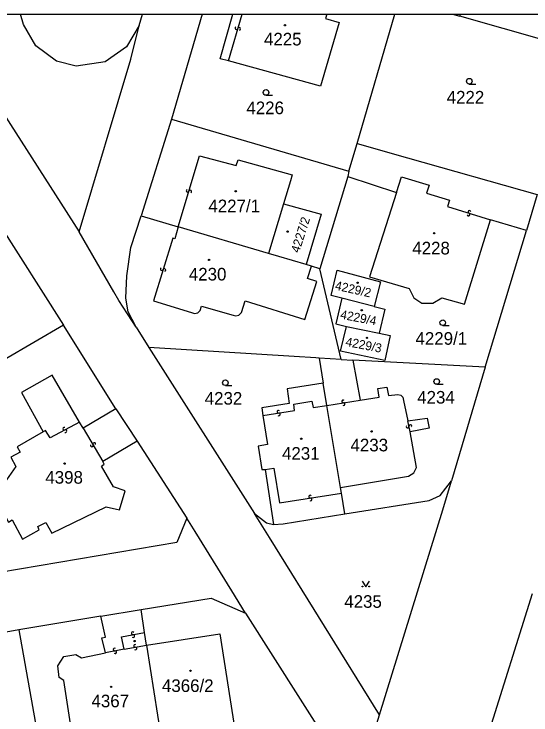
# Model space of a CAD drawing. Extents: x -600391 to -599491, y -1160176 to -1159402.
# Drawn here: x -600015.6 to -599946, y -1159496.1 to -1159401.8 of the extents above; entities that cross this region are included whole.
import ezdxf

# ---------------------------------------------------------------- set-up
doc = ezdxf.new("R2010")
doc.units = 0
for name, color, linetype in [('Level 1', 7, 'Continuous'), ('Level 13', 7, 'Continuous'), ('Level 3', 7, 'Continuous'), ('Level 4', 7, 'Continuous'), ('Level 5', 7, 'Continuous'), ('Vrstva 63', 7, 'Continuous')]:
    doc.layers.add(name, color=color, linetype=linetype)

msp = doc.modelspace()

# ---------------------------------------------------------------- linework, layer by layer
at = {"layer": 'Level 1'}
for p, q in [((-600025.615, -1159401.769), (-600006.83, -1159431.1)), ((-599998.75, -1159403.33), (-599998.285, -1159401.769)), ((-599990.249, -1159401.769), (-599994.38, -1159415.94)), ((-599969.4, -1159419.22), (-599964.303, -1159401.769)), ((-599956.549, -1159401.769), (-599955.56, -1159402.05))]:
    msp.add_line(p, q, dxfattribs=at)
for points in [[(-599998.75, -1159403.33), (-600000.47, -1159406.19), (-600003.32, -1159408.19), (-600007.23, -1159408.8), (-600009.86, -1159408.12), (-600012.67, -1159406.06), (-600014.33, -1159403.17), (-600014.711, -1159401.769)], [(-599986.74, -1159408.06), (-599987.82, -1159407.78), (-599986.115, -1159401.769)], [(-599973.501, -1159401.769), (-599973.67, -1159402.38), (-599971.8, -1159402.92), (-599974.35, -1159411.47), (-599986.74, -1159408.06)], [(-599943.91, -1159405.37), (-599955.56, -1159402.05)], [(-600006.83, -1159431.1), (-599999.85, -1159407.83), (-599998.75, -1159403.33)], [(-599994.38, -1159415.94), (-599998.47, -1159428.92)], [(-599994.38, -1159415.94), (-599970.52, -1159422.92)], [(-599970.52, -1159422.92), (-599969.4, -1159419.22)], [(-599969.4, -1159419.22), (-599962.6, -1159421.11), (-599945.15, -1159426.05)], [(-599970.52, -1159422.92), (-599970.67, -1159423.65)], [(-599970.67, -1159423.65), (-599974.42, -1159436.05)], [(-599970.67, -1159423.65), (-599964.11, -1159425.81)], [(-599964.11, -1159425.81), (-599967.72, -1159437.15), (-599962.41, -1159438.72), (-599961.78, -1159439.97), (-599960.68, -1159440.68), (-599959.19, -1159440.71), (-599958, -1159439.98), (-599954.96, -1159440.83), (-599951.46, -1159429.47)], [(-599945.15, -1159426.05), (-599946.61, -1159430.9)], [(-599979.31, -1159427.32), (-599981.35, -1159434)], [(-599979.31, -1159427.32), (-599974.26, -1159428.69), (-599976.27, -1159435.47)], [(-599999.17, -1159443.94), (-600000.24, -1159441.85), (-600000.55, -1159440.01), (-600000.42, -1159436.99), (-599999.85, -1159433.21), (-599998.47, -1159428.92)], [(-599998.47, -1159428.92), (-599993.49, -1159430.4)], [(-600017.83, -1159429.73), (-600008.95, -1159443.66)], [(-599946.61, -1159430.9), (-599951.46, -1159429.47)], [(-599999.17, -1159443.94), (-600001.48, -1159440.33), (-600002.16, -1159439.16), (-600006.83, -1159431.1)], [(-599981.35, -1159434), (-599993.49, -1159430.4)], [(-599952.16, -1159449.29), (-599946.61, -1159430.9)], [(-599976.27, -1159435.47), (-599979.93, -1159434.39), (-599981.35, -1159434)], [(-599975.55, -1159435.7), (-599976.27, -1159435.47)], [(-599974.42, -1159436.05), (-599975.55, -1159435.7)], [(-599971.57, -1159448.28), (-599974.42, -1159436.05)], [(-599971.45, -1159440), (-599972.91, -1159439.66), (-599972.1, -1159436.26), (-599966.26, -1159437.8), (-599967.11, -1159441.12)], [(-599971.45, -1159440), (-599972.28, -1159443.48), (-599970.83, -1159443.84)], [(-599967.11, -1159441.12), (-599971.45, -1159440)], [(-599967.11, -1159441.12), (-599965.67, -1159441.52), (-599966.43, -1159444.74)], [(-600008.95, -1159443.66), (-600024.96, -1159452.99)], [(-600001.88, -1159454.91), (-600008.95, -1159443.66)], [(-599999.17, -1159443.94), (-599997.46, -1159446.65)], [(-599966.43, -1159444.74), (-599964.95, -1159445.06), (-599965.67, -1159448.43), (-599971.62, -1159447.16), (-599970.83, -1159443.84)], [(-599970.83, -1159443.84), (-599966.43, -1159444.74)], [(-599997.46, -1159446.65), (-599983.21, -1159469.02)], [(-599974.53, -1159448.1), (-599974.95, -1159448.07), (-599977.9, -1159447.88), (-599997.46, -1159446.65)], [(-599974.53, -1159448.1), (-599973.98, -1159451.47)], [(-599971.57, -1159448.28), (-599974.53, -1159448.1)], [(-599971.57, -1159448.28), (-599969.96, -1159448.36)], [(-599969.96, -1159448.36), (-599968.99, -1159453.75)], [(-599952.16, -1159449.29), (-599969.96, -1159448.36)], [(-599952.16, -1159449.29), (-599956.69, -1159464.61)], [(-600006.79, -1159456.69), (-600010.47, -1159450.38), (-600014.61, -1159452.7), (-600011.66, -1159458.03)], [(-599973.98, -1159451.47), (-599978.83, -1159452.23), (-599978.53, -1159454.19), (-599982.25, -1159454.77), (-599982.09, -1159455.82)], [(-599973.49, -1159454.45), (-599973.98, -1159451.47)], [(-599968.99, -1159453.75), (-599966.44, -1159453.34), (-599966.62, -1159452.18), (-599965.39, -1159451.99), (-599965.18, -1159453.11), (-599963.9, -1159452.97), (-599963.51, -1159453.07), (-599963.23, -1159453.34), (-599963.14, -1159453.8), (-599962.57, -1159456.54)], [(-599971.66, -1159465.49), (-599973.49, -1159454.45)], [(-600001.88, -1159454.91), (-600006.28, -1159457.51)], [(-600001.88, -1159454.91), (-599999.04, -1159459.27)], [(-599982.09, -1159455.82), (-599981.49, -1159459.72), (-599982.73, -1159459.94), (-599982.22, -1159463.09), (-599981.8, -1159463.06)], [(-599962.57, -1159456.54), (-599959.95, -1159456.18), (-599959.7, -1159457.53), (-599962.27, -1159457.99)], [(-600006.28, -1159457.51), (-600006.79, -1159456.69)], [(-600011.66, -1159458.03), (-600015.18, -1159460.01), (-600014.76, -1159460.73), (-600016.04, -1159461.43), (-600015.37, -1159462.68), (-600016.63, -1159464.47), (-600018.81, -1159465.7), (-600016.35, -1159470.15), (-600015.87, -1159469.86), (-600014.45, -1159472.45), (-600012.22, -1159471.19), (-600012.41, -1159470.77), (-600011.32, -1159470.22), (-600010.53, -1159471.65), (-600003.19, -1159468.1), (-600001.39, -1159468.5), (-600000.63, -1159465.94), (-600002.22, -1159465.43), (-600003.82, -1159462.61), (-600003.46, -1159462.37), (-600003.64, -1159461.99)], [(-599971.66, -1159465.49), (-599962.5, -1159463.98), (-599961.77, -1159463.52), (-599961.42, -1159462.82), (-599962.27, -1159457.99)], [(-599999.04, -1159459.27), (-600003.64, -1159461.99)], [(-599999.04, -1159459.27), (-599992.35, -1159469.62)], [(-599981.8, -1159463.06), (-599980.66, -1159470.47)], [(-599971.05, -1159469.06), (-599959.69, -1159467.25), (-599958.23, -1159466.59), (-599956.69, -1159464.61)], [(-599966.37, -1159496.11), (-599957.84, -1159468.5), (-599956.69, -1159464.61)], [(-599971.51, -1159466.28), (-599971.66, -1159465.49)], [(-599971.05, -1159469.06), (-599971.51, -1159466.28)], [(-599992.35, -1159469.62), (-599993.67, -1159472.9), (-600020.2, -1159477.39)], [(-599984.41, -1159482.41), (-599986.27, -1159479.41), (-599991.22, -1159471.43), (-599992.35, -1159469.62)], [(-599966.37, -1159496.11), (-599981.19, -1159472.22), (-599983.21, -1159469.02)], [(-599983.21, -1159469.02), (-599981.59, -1159470.25), (-599980.66, -1159470.47)], [(-599980.66, -1159470.47), (-599979.38, -1159470.39), (-599971.05, -1159469.06)], [(-599951.75, -1159498.81), (-599945.8, -1159479.77)], [(-599998.49, -1159481.92), (-599989.04, -1159480.4), (-599984.41, -1159482.41)], [(-600003.91, -1159482.81), (-599998.49, -1159481.92)], [(-599998.02, -1159485.04), (-599998.49, -1159481.92)], [(-600003.91, -1159482.81), (-600014.96, -1159484.67)], [(-600003.27, -1159487.74), (-600003.77, -1159485.72), (-600003.29, -1159485.64), (-600003.91, -1159482.81)], [(-599984.41, -1159482.41), (-599969.39, -1159506.08)], [(-600014.96, -1159484.67), (-600043.93, -1159490), (-600048.97, -1159491.15), (-600051.13, -1159491.64), (-600057.82, -1159493.18), (-600069.07, -1159496.17)], [(-600014.96, -1159484.67), (-600008.62, -1159520.17)], [(-599997.77, -1159486.73), (-599998.02, -1159485.04)], [(-599997.77, -1159486.73), (-599987.88, -1159485.19), (-599985.93, -1159497.81), (-599986.24, -1159497.89)], [(-599997.77, -1159486.73), (-599995.79, -1159499.31)], [(-600000.15, -1159500.17), (-600004.68, -1159501.02), (-600004.93, -1159501.44), (-600006.89, -1159501.81), (-600008.07, -1159500.65), (-600008.3, -1159498.98), (-600007.82, -1159498.47), (-600008.9, -1159491.47), (-600009.52, -1159491.06), (-600009.72, -1159489.5), (-600008.87, -1159488.26), (-600007.29, -1159487.98), (-600006.51, -1159488.42), (-600003.27, -1159487.74)], [(-599969.39, -1159506.08), (-599968.93, -1159504.55), (-599966.73, -1159497.29), (-599966.37, -1159496.11)]]:
    msp.add_lwpolyline(points, dxfattribs=at)
at = {"layer": 'Level 13'}
for centre, start, end in [((-599985.646, -1159403.676), 111.0083, 343.1063), ((-599985.294, -1159403.783), 290.79384, 163.38384), ((-599992.226, -1159425.565), 110.59096, 342.68896), ((-599991.874, -1159425.674), 290.37651, 162.96651), ((-599954.284, -1159428.404), 20.263, 252.361), ((-599954.395, -1159428.756), 200.04855, 72.63855), ((-599995.706, -1159436.115), 109.97449, 342.56449), ((-599995.354, -1159436.226), 290.18894, 162.28694), ((-599971.267, -1159453.917), 46.21455, 278.31254), ((-599971.213, -1159454.282), 226.00009, 98.59009), ((-599979.987, -1159455.307), 46.19992, 278.29792), ((-599979.933, -1159455.672), 225.98547, 98.57547), ((-600008.856, -1159457.588), 65.43314, 298.02314), ((-599962.601, -1159457.306), 139.0621, 11.1601), ((-599962.24, -1159457.234), 318.84765, 191.43765), ((-600008.684, -1159457.913), 245.6476, 117.74559), ((-600005.119, -1159459.843), 157.66852, 30.25852), ((-600004.8, -1159459.658), 337.88297, 209.98097), ((-599975.716, -1159466.737), 46.14464, 278.24264), ((-599975.663, -1159467.102), 225.93019, 98.52019), ((-599999.61, -1159485.138), 47.37024, 279.46823), ((-599999.549, -1159485.501), 227.15578, 99.74578), ((-599999.311, -1159486.818), 47.54352, 279.64151), ((-600002.053, -1159487.319), 47.84738, 280.43738), ((-600001.987, -1159487.682), 228.06184, 100.15984), ((-599999.248, -1159487.181), 227.32906, 99.91906)]:
    msp.add_arc(centre, 0.184, start, end, dxfattribs=at)
at = {"layer": 'Level 3'}
for p, q in [((-599986.74, -1159408.06), (-599984.893, -1159401.769)), ((-599955.56, -1159402.05), (-599955.479, -1159401.769))]:
    msp.add_line(p, q, dxfattribs=at)
for points in [[(-599993.49, -1159430.4), (-599990.61, -1159420.85), (-599985.67, -1159422.15), (-599985.41, -1159421.38), (-599978.14, -1159423.4), (-599978.38, -1159424.23), (-599979.31, -1159427.32)], [(-599964.11, -1159425.81), (-599963.44, -1159423.67), (-599959.71, -1159424.81), (-599960.06, -1159425.89), (-599956.98, -1159426.84), (-599957.21, -1159427.7), (-599951.46, -1159429.47)], [(-599993.49, -1159430.4), (-599993.96, -1159432.03), (-599994.23, -1159431.95), (-599996.84, -1159440.39), (-599991.69, -1159441.94), (-599991.28, -1159442.06), (-599990.86, -1159442.01), (-599990.54, -1159441.68), (-599990.37, -1159441.1), (-599986.1, -1159442.3), (-599985.72, -1159442.38), (-599985.34, -1159442.29), (-599984.97, -1159441.95), (-599984.48, -1159440.38), (-599976.43, -1159442.91), (-599974.84, -1159437.78), (-599976.07, -1159437.36), (-599975.55, -1159435.7)], [(-599973.49, -1159454.45), (-599968.99, -1159453.75)], [(-599982.09, -1159455.82), (-599977.84, -1159455.16), (-599977.94, -1159454.3), (-599975.5, -1159453.89), (-599975.33, -1159454.75), (-599973.49, -1159454.45)], [(-599962.27, -1159457.99), (-599962.57, -1159456.54)], [(-600006.79, -1159456.69), (-600010.75, -1159458.82), (-600011.34, -1159457.83), (-600011.66, -1159458.03)], [(-600006.28, -1159457.51), (-600003.64, -1159461.99)], [(-599981.8, -1159463.06), (-599980.6, -1159462.89), (-599979.87, -1159467.57), (-599971.51, -1159466.28)], [(-600000.78, -1159487.27), (-600001.14, -1159485.59), (-599998.02, -1159485.04)], [(-600000.78, -1159487.27), (-599997.77, -1159486.73)], [(-600000.78, -1159487.27), (-600003.27, -1159487.74)]]:
    msp.add_lwpolyline(points, dxfattribs=at)
at = {"layer": 'Level 5'}
for p, q in [((-599954.3, -1159411.19), (-599953.425, -1159411.19)), ((-599981.66, -1159412.7), (-599980.785, -1159412.7)), ((-599957.87, -1159443.7), (-599956.995, -1159443.7)), ((-599987.14, -1159451.78), (-599986.265, -1159451.78)), ((-599958.68, -1159451.61), (-599957.805, -1159451.61))]:
    msp.add_line(p, q, dxfattribs=at)
msp.add_lwpolyline([(-599968.741, -1159478.12), (-599968.24, -1159478.87), (-599967.74, -1159478.12)], dxfattribs=at)
for centre, radius in [((-599979.12, -1159403.28), 0.09), ((-599979.12, -1159403.28), 0.0521), ((-599954.3, -1159410.815), 0.375), ((-599981.66, -1159412.325), 0.375), ((-599985.75, -1159425.63), 0.09), ((-599985.75, -1159425.63), 0.0521), ((-599978.77, -1159431.06), 0.09), ((-599978.77, -1159431.06), 0.0521), ((-599959.03, -1159431.29), 0.09), ((-599959.03, -1159431.29), 0.0521), ((-599989.33, -1159434.87), 0.09), ((-599989.33, -1159434.87), 0.0521), ((-599969.34, -1159437.94), 0.09), ((-599969.34, -1159437.94), 0.0521), ((-599968.78, -1159441.65), 0.09), ((-599968.78, -1159441.65), 0.0521), ((-599957.87, -1159443.325), 0.375), ((-599968.07, -1159445.36), 0.09), ((-599968.07, -1159445.36), 0.0521), ((-599958.68, -1159451.235), 0.375), ((-599987.14, -1159451.405), 0.375), ((-599967.46, -1159457.96), 0.09), ((-599967.46, -1159457.96), 0.0521), ((-599976.92, -1159458.94), 0.09), ((-599976.92, -1159458.94), 0.0521), ((-600008.79, -1159462.28), 0.09), ((-600008.79, -1159462.28), 0.0521), ((-599968.69, -1159478.82), 0.05), ((-599967.791, -1159478.82), 0.05), ((-599999.37, -1159486.17), 0.09), ((-599999.37, -1159486.17), 0.0521), ((-599991.84, -1159490.16), 0.09), ((-599991.84, -1159490.16), 0.0521), ((-600002.52, -1159492.35), 0.09), ((-600002.52, -1159492.35), 0.0521)]:
    msp.add_circle(centre, radius, dxfattribs=at)
at = {"layer": 'Vrstva 63'}
msp.add_lwpolyline([(-600391.008, -1159401.769), (-599490.773, -1159401.769), (-599490.773, -1160176.079), (-600391.008, -1160176.079)], close=True, dxfattribs=at)

# ---------------------------------------------------------------- texts
at = {"layer": 'Level 4'}
for s, p in [('4225', (-599981.94, -1159406)), ('4222', (-599957.34, -1159413.82)), ('4226', (-599984.31, -1159415.25)), ('4227/1', (-599989.43, -1159428.45)), ('4228', (-599961.97, -1159434.13)), ('4230', (-599992.06, -1159437.64)), ('4229/1', (-599961.54, -1159446.29)), ('4232', (-599989.92, -1159454.35)), ('4234', (-599961.31, -1159454.21)), ('4233', (-599970.29, -1159460.64)), ('4231', (-599979.51, -1159461.76)), ('4398', (-600011.38, -1159464.99)), ('4235', (-599971.13, -1159481.7)), ('4366/2', (-599995.68, -1159493.03)), ('4367', (-600005.17, -1159495.09))]:
    msp.add_text(s, height=1.7, dxfattribs=at).set_placement(p)
for s, rotation, p in [('4227/2', 72.34506, (-599977.21, -1159434)), ('4229/2', 347.37057, (-599972.46, -1159438.85)), ('4229/4', 349.01136, (-599971.74, -1159442.76)), ('4229/3', 349.01136, (-599971.03, -1159446.43))]:
    msp.add_text(s, height=1.2, rotation=rotation, dxfattribs=at).set_placement(p)

doc.saveas('drawing.dxf')
